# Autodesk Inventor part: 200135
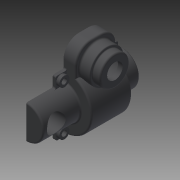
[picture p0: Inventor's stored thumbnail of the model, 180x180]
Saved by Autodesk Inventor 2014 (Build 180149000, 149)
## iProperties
Created: 2007-11
Part Number: 200135
Document SubType Name: Modeling
Designer: JJ
Density: 1.06 g/cm^3
Mass: 15.4479 g
Surface Area: 94.4063 cm^2
Volume: 14.5735 cm^3
Material: ABS Plastic
Description: GEAR  HOUSING CASE SIDE 2
Appearance: Gray
Component Category: Lower Component
Author: JJ
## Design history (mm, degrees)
sketch "Sketch1"
  geometry: C1 r 11 at (0, 0); 1 further point
  constraints: 1 centre point, 1 coincident
  dimensions: "d0" = 22 diameter of C1
extrude "Extrusion1" new body sketch "Sketch1" distance "d1" = 62; taper "d2" = 0 deg
workplane "Work Plane1"
sketch "Sketch2"
  geometry: C1 r 11 at (0, 0) reference; C2 r 18 at (0, 0)
  constraints: 1 centre point, 1 coincident
  dimensions: "d4" = 36 diameter of C2
extrude "Extrusion2" join sketch "Sketch2" distance "d5" = 26; taper "d6" = 0 deg
sketch "Sketch3"
  geometry: L1 (50, -18)-(24, -18) reference; L2 (24, -18)-(24, -11) reference; L3 (24, -11)-(0, -11) reference; L4 (0, -11)-(0, 11) reference; L5 (0, 11)-(24, 11) reference; L6 (24, 11)-(24, 18) reference; L7 (24, 18)-(50, 18) reference; L8 (50, 18)-(50, 11) reference; L9 (50, 11)-(62, 11) reference; L10 (62, 11)-(62, -11) reference; L11 (62, -11)-(50, -11) reference; L12 (50, -11)-(50, -18) reference; L13 (0, 0)-(62, 0); L14 (24, 18)-(50, 18); L15 (50, 18)-(50, 33); L16 (50, 33)-(24, 33); L17 (24, 33)-(24, 18); L18 (24, 18)-(50, 18); L19 (50, 18)-(50, 14.5); L20 (50, 14.5)-(24, 14.5); L21 (24, 14.5)-(24, 18); L22 (56, 9.05)-(41.5, 9.05); L23 (17.85, 9.05)-(17.85, 0); L24 (62, 4.05)-(56, 4.05); L25 (56, 4.05)-(56, 9.05); L26 (32.5, 9.05)-(17.85, 9.05); L27 (41.5, 9.05)-(41.5, 16); L28 (32.5, 16)-(41.5, 16); L29 (32.5, 16)-(32.5, 9.05); L30 (17.85, 0)-(62, 0); L31 (62, 0)-(62, 4.05); C1 r 11 at (37, 20); C2 r 9.5 at (37, 20); C3 r 8.5 at (37, 20); C4 r 6 at (8.375, 0); 3 further points
  constraints: 38 end point, 5 midpoint, 5 parallel, 4 centre point, 4 perpendicular, 4 point on line, 2 coincident, 2 collinear, 2 horizontal, 1 vertical alignment, 1 other
  dimensions: "d7" = 22 diameter of C1; "d8" = 20 distance from line of C1.centre L13; "d9" = 15 distance of L14.end L15.end; "d10" = 13 distance from line of C1.centre L6; "d15" = 19 diameter of C2; "d16" = 17 diameter of C3; "d25" = 9.05 distance of L23.start L23.end; "d26" = 9 distance between parallel lines of L27 L29 (computed from d16); "d28" = 6 distance between parallel lines of L10 L25; "d29" = 4.05 distance between parallel lines of L30 L24; "d30" = 2 distance between parallel lines of L7 L28; "d31" = 14.65 distance between parallel lines of L29 L23; "d34" = 12 diameter of C4; "d35" = 8.37473 distance from line of L4 C4.centre (derived); "d67" = 26 distance of L15.end L16.end (derived); "d99" = 0.62527 distance of point (37.625, 20) C1.centre (derived)
  node "Project Cut Edges2"
extrude "Extrusion3" join sketch "Sketch3" stored distance "d11" = 16; taper "d12" = 0 deg
extrude "Extrusion4" join sketch "Sketch3" stored distance "d13" = 30; taper "d14" = 0 deg
extrude "Extrusion5" join sketch "Sketch3" stored distance "d17" = 40; taper "d18" = 0 deg
extrude "Extrusion6" cut sketch "Sketch3" stored distance "d19" = 34; taper "d20" = 0 deg
revolve "Revolution1" stored, may be unused: angle "d32" = 90 deg
split "Split1"
extrude "Extrusion7" cut sketch "Sketch3" stored distance "d36" = 56; taper "d37" = 0 deg
sketch "Sketch4"
  geometry: C1 r 9.5 at (0, 0) reference; C2 r 5 at (0, 0)
  constraints: 1 centre point, 1 coincident
  dimensions: "d40" = 10 diameter of C2
extrude "Extrusion8" cut sketch "Sketch4" stored distance "d41" = 56; taper "d42" = 0 deg
fillet "Fillet7" dims "d47" = 10
fillet "Fillet8" dims "d48" = 1
fillet "Fillet9" dims "d49" = 0.5
sketch "Sketch5"
  geometry: L1 (9, -13)-(-3, -13) reference; L2 (9, -13)-(2, -13); L3 (2, -13)-(2, -20); L4 (2, -20)-(9, -20); L5 (9, -20)-(9, -13); L6 (9, -20)-(11, -20); L7 (11, -20)-(11, -13); L8 (11, -13)-(9, -13); L9 (9, -13)-(9, -20); L10 (-13, -3)-(-13, 3) reference; L11 (-3, 13)-(9, 13) reference; L12 (-13, 0)-(-30.7, 0); L13 (20, -28.625)-(20, -23.982); L14 (9, 13)-(2, 13); L15 (2, 13)-(2, 20); L16 (2, 20)-(9, 20); L17 (9, 20)-(9, 13); L18 (11, 13)-(9, 13); L19 (9, 20)-(11, 20); L20 (11, 20)-(11, 13); L21 (9, 13)-(9, 20); L22 (31, -13)-(38, -13); L23 (38, -13)-(38, -20); L24 (38, -20)-(31, -20); L25 (31, -20)-(31, -13); L26 (31, -20)-(29, -20); L27 (29, -20)-(29, -13); L28 (29, -13)-(31, -13); L29 (31, -13)-(31, -20); L30 (31, 20)-(31, 13); L31 (31, 13)-(31, 20); L32 (29, 20)-(29, 13); L33 (31, 20)-(29, 20); L34 (38, 20)-(31, 20); L35 (38, 13)-(38, 20); L36 (31, 13)-(38, 13); L37 (29, 13)-(31, 13); C1 r 6 at (20, -28.625) reference; C2 r 3.25 at (34.5, -16.5); C3 r 3.25 at (34.5, 16.5); C4 r 3.25 at (5.5, 16.5); C5 r 3.25 at (5.5, -16.5); 7 further points
  constraints: 68 end point, 25 symmetric about line, 5 parallel, 4 centre point, 4 coincident, 3 perpendicular, 2 horizontal, 1 midpoint, 1 point on line
  dimensions: "d51" = 7 distance between parallel lines of L2 L4 (= d52); "d52" = 7 distance of L3.end L4.end; "d53" = 3.5 distance from line of L4 point (5.5, -16.5) (= 0.5 x d51); "d54" = 3.5 distance from line of L3 point (5.5, -16.5) (= 0.5 x d52); "d78" = 6.5 diameter of C2; "d79" = 6.5 diameter of C3 (= d78); "d80" = 6.5 diameter of C4 (= d78); "d81" = 6.5 diameter of C5 (= d78); "d91" = 2 distance between parallel lines of L9 L7
extrude "Extrusion9" join sketch "Sketch5" distance "d56" = 2; taper "d57" = 0 deg
extrude "Extrusion11" join sketch "Sketch5" distance "d82" = 4; taper "d83" = 0 deg
hole "Hole2" sketch "Sketch5" diameter "d84" = 3.4; stored, may be unused: countersink angle "d88" = 90 deg, drill point angle "d90" = 118 deg; dims "d85" = 6, "d86" = 6.3, "d87" = 2, "d89" = 4
chamfer "Chamfer1" distance "d92" = 0.5; stored, may be unused: second distance "d93" = 2, angle "d94" = 45 deg
fillet "Fillet13" dims "d95" = 1
fillet "Fillet14" dims "d96" = 1
fillet "Fillet15" dims "d97" = 1
mirror "Mirror1"
body "Solid1"
node "Project Cut Edges1"
other parameters: "d3" = -24
